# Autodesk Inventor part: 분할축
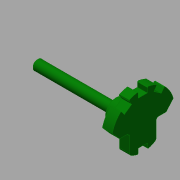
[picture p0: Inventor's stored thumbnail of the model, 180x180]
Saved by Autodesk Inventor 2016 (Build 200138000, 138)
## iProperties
Created: 2016-11
Part Number: 분할축
Material: 강철, 연강
Document SubType Name: Modeling
Designer: mduedu
Density: 1 g/cm^3
Appearance: 진녹색
Author: mduedu
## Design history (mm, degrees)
sketch "스케치1"
  geometry: C1 r 38 at (0, 0); 1 further point
  constraints: 1 centre point, 1 coincident
  dimensions: "d0" = 76 diameter of C1
extrude "돌출1" new body sketch "스케치1" distance "d1" = 12; taper "d2" = 0 deg
sketch "스케치2"
  geometry: L1 (0, 38)-(0, -38); L2 (5.5, 37.6)-(5.5, 31); L3 (5.5, 31)-(-5.5, 31); L4 (-5.5, 31)-(-5.5, 37.6); A1 r 38 centre (0, 0) between (0, 38) and (0, -38) reference; A2 r 38 centre (0, 0) between (5.5, 37.6) and (-5.5, 37.6); 2 further points
  constraints: 8 end point, 6 point on circle, 2 coincident, 2 vertical, 1 centre point, 1 horizontal, 1 midpoint, 1 parallel, 1 symmetric about line
  dimensions: "d3" = 11 distance of L2.end L3.end; "d5" = 31 distance from line of L3 point (0, 0)
extrude "돌출2" cut sketch "스케치2" stored distance "d7" = 12; taper "d8" = 0 deg
sketch "스케치3"
  geometry: L1 (-16, 0)-(-38, 0); L2 (16, 0)-(38, 0); L3 (0, -28)-(0, 28); L4 (-16, -22.978)-(-16, 0); L5 (16, -22.978)-(16, 0); A1 r 38 centre (0, 0) between (-5.5, 37.6) and (-17.061, 33.955) reference; A2 r 38 centre (0, 0) between (-38, 0) and (38, 0); A3 r 28 centre (0, 0) between (-16, -22.978) and (16, -22.978); 4 further points
  constraints: 10 end point, 7 point on circle, 3 coincident, 2 centre point, 2 horizontal alignment, 2 midpoint, 2 parallel, 1 collinear, 1 horizontal, 1 perpendicular, 1 other
  dimensions: "d13" = 32 distance between parallel lines of L5 L4; "d14" = 28 radius of A3
extrude "돌출3" cut sketch "스케치3" stored distance "d15" = 12; taper "d16" = 0 deg
sketch "스케치4"
  geometry: L1 (0, 0)-(0, -28); L2 (5.5, -27.455)-(5.5, -21); L3 (5.5, -21)-(-5.5, -21); L4 (-5.5, -21)-(-5.5, -27.455); A1 r 28 centre (0, 0) between (-16, -22.978) and (16, -22.978) reference; A2 r 28 centre (0, 0) between (16, -22.978) and (0, -28); A3 r 28 centre (0, 0) between (-5.5, -27.455) and (5.5, -27.455); 1 further point
  constraints: 8 end point, 7 point on circle, 2 centre point, 2 coincident, 1 horizontal, 1 parallel, 1 other
  dimensions: "d17" = 11 distance between parallel lines of L2 L4; "d19" = 21 distance from line of L3 point (0, 0)
extrude "돌출4" cut sketch "스케치4" stored distance "d20" = 12; taper "d21" = 0 deg
sketch "스케치5"
  geometry: C1 r 13 at (0, 0); 1 further point
  constraints: 1 centre point, 1 coincident
  dimensions: "d22" = 26 diameter of C1
extrude "돌출5" join sketch "스케치5" distance "d23" = 20; taper "d24" = 0 deg
sketch "스케치6"
  geometry: C1 r 6 at (0, 0); 1 further point
  constraints: 1 centre point, 1 coincident
  dimensions: "d25" = 12 diameter of C1
extrude "돌출6" join sketch "스케치6" distance "d26" = 95; taper "d27" = 0 deg
fillet "모깎기1" dims "d28" = 3
chamfer "모따기1" distance "d29" = 1; stored, may be unused: second distance "d30" = 2, angle "d31" = 45 deg
sketch "스케치7"
  geometry: L1 (-20, 13)-(-20, -13) reference; L2 (-20, 6)-(-114, 6) reference; L3 (0, 0)-(-20, 0); C1 r 1 at (-21, 6)
  constraints: 2 end point, 1 centre point, 1 midpoint, 1 tangent
  dimensions: "d32" = 2 diameter of C1; "d33" = 10 dimension on C1 L3
revolve "회전1" sketch "스케치7" stored, may be unused: angle "d34" = 90 deg
chamfer "모따기2" distance "d35" = 1; stored, may be unused: second distance "d36" = 2, angle "d37" = 45 deg
chamfer "모따기3" distance "d38" = 10; stored, may be unused: second distance "d39" = 2, angle "d40" = 45 deg
chamfer "모따기4" distance "d41" = 1; stored, may be unused: second distance "d42" = 2, angle "d43" = 45 deg
fillet "모깎기2" dims "d44" = 3
node "솔리드1"
pattern_circular "원형 패턴1" dims angle "d10" = 35 deg
other parameters: "d12" = 56
